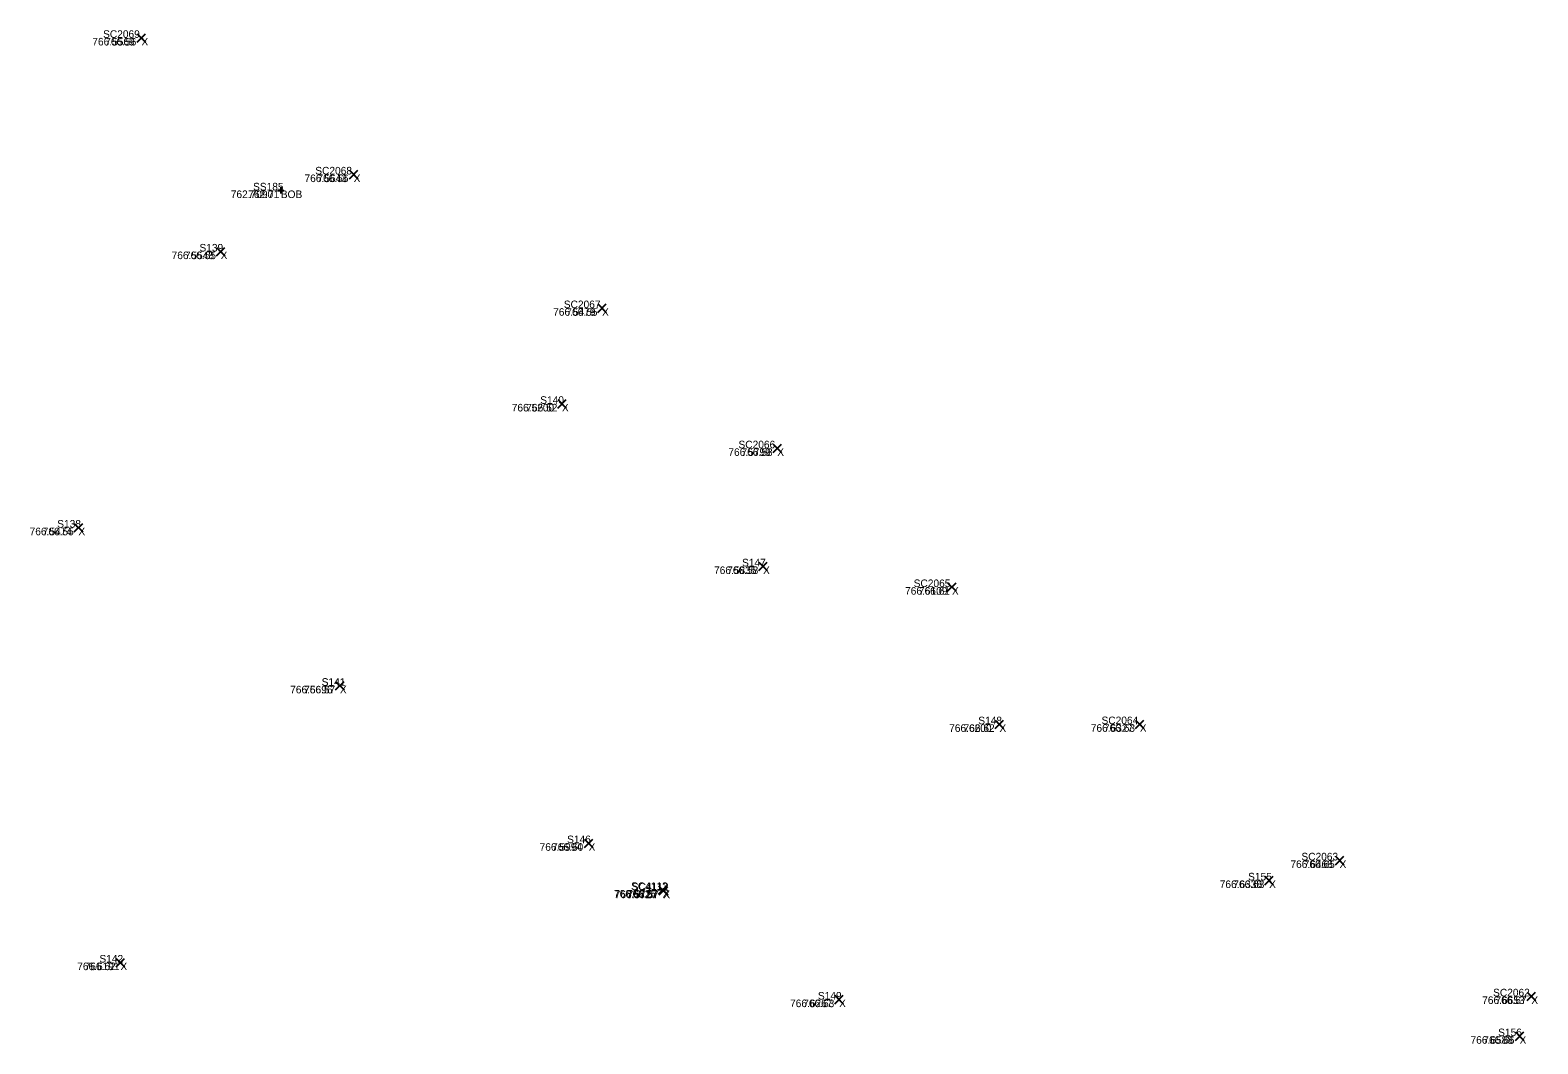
# Model space of a CAD drawing. Extents: x 1845019 to 1877956, y 680444 to 701081.
# Drawn here: x 1857583.62 to 1857595.52, y 694342.22 to 694350.22 of the extents above; entities that cross this region are included whole.
import ezdxf

# ---------------------------------------------------------------- set-up
doc = ezdxf.new("R2010")
doc.units = 0
for name, color, linetype in [('BR_X_SV_Bottom_of_Beam_Text', 7, 'Continuous'), ('SV_X_Random_Point', 7, 'Continuous'), ('SV_X_Text_Comment', 7, 'Continuous'), ('SV_X_Text_Elevation', 7, 'Continuous'), ('SV_X_Text_Name', 7, 'Continuous')]:
    doc.layers.add(name, color=color, linetype=linetype)

msp = doc.modelspace()

# ---------------------------------------------------------------- linework, layer by layer
at = {"layer": 'BR_X_SV_Bottom_of_Beam_Text'}
for p, q in [((1857585.572, 694348.951), (1857585.622, 694348.951)), ((1857585.572, 694348.951), (1857585.622, 694348.951)), ((1857585.597, 694348.976), (1857585.597, 694348.926)), ((1857585.597, 694348.976), (1857585.597, 694348.926)), ((1857585.597, 694348.951), (1857585.597, 694348.951)), ((1857585.597, 694348.951), (1857585.597, 694348.951))]:
    msp.add_line(p, q, dxfattribs=at)
at = {"layer": 'SV_X_Random_Point'}
for p, q in [((1857584.463, 694350.122), (1857584.53, 694350.188)), ((1857584.463, 694350.188), (1857584.53, 694350.122)), ((1857584.463, 694350.122), (1857584.53, 694350.188)), ((1857584.463, 694350.188), (1857584.53, 694350.122)), ((1857586.138, 694349.043), (1857586.205, 694349.11)), ((1857586.138, 694349.11), (1857586.205, 694349.043)), ((1857586.138, 694349.043), (1857586.205, 694349.11)), ((1857586.138, 694349.11), (1857586.205, 694349.043)), ((1857585.089, 694348.436), (1857585.156, 694348.502)), ((1857585.089, 694348.502), (1857585.156, 694348.436)), ((1857585.089, 694348.436), (1857585.156, 694348.502)), ((1857585.089, 694348.502), (1857585.156, 694348.436)), ((1857588.099, 694347.989), (1857588.166, 694348.055)), ((1857588.099, 694348.055), (1857588.166, 694347.989)), ((1857588.099, 694347.989), (1857588.166, 694348.055)), ((1857588.099, 694348.055), (1857588.166, 694347.989)), ((1857587.783, 694347.233), (1857587.85, 694347.3)), ((1857587.783, 694347.3), (1857587.85, 694347.233)), ((1857587.783, 694347.233), (1857587.85, 694347.3)), ((1857587.783, 694347.3), (1857587.85, 694347.233)), ((1857589.483, 694346.883), (1857589.549, 694346.949)), ((1857589.483, 694346.949), (1857589.549, 694346.883)), ((1857589.483, 694346.883), (1857589.549, 694346.949)), ((1857589.483, 694346.949), (1857589.549, 694346.883)), ((1857583.966, 694346.256), (1857584.033, 694346.323)), ((1857583.966, 694346.323), (1857584.033, 694346.256)), ((1857583.966, 694346.256), (1857584.033, 694346.323)), ((1857583.966, 694346.323), (1857584.033, 694346.256)), ((1857589.37, 694345.951), (1857589.437, 694346.018)), ((1857589.37, 694346.018), (1857589.437, 694345.951)), ((1857589.37, 694345.951), (1857589.437, 694346.018)), ((1857589.37, 694346.018), (1857589.437, 694345.951)), ((1857590.861, 694345.788), (1857590.928, 694345.854)), ((1857590.861, 694345.854), (1857590.928, 694345.788)), ((1857590.861, 694345.788), (1857590.928, 694345.854)), ((1857590.861, 694345.854), (1857590.928, 694345.788)), ((1857586.029, 694345.009), (1857586.096, 694345.076)), ((1857586.029, 694345.076), (1857586.096, 694345.009)), ((1857586.029, 694345.009), (1857586.096, 694345.076)), ((1857586.029, 694345.076), (1857586.096, 694345.009)), ((1857591.236, 694344.704), (1857591.303, 694344.771)), ((1857591.236, 694344.771), (1857591.303, 694344.704)), ((1857591.236, 694344.704), (1857591.303, 694344.771)), ((1857591.236, 694344.771), (1857591.303, 694344.704)), ((1857592.344, 694344.706), (1857592.411, 694344.772)), ((1857592.344, 694344.772), (1857592.411, 694344.706)), ((1857592.344, 694344.706), (1857592.411, 694344.772)), ((1857592.344, 694344.772), (1857592.411, 694344.706)), ((1857587.994, 694343.766), (1857588.061, 694343.833)), ((1857587.994, 694343.833), (1857588.061, 694343.766)), ((1857587.994, 694343.766), (1857588.061, 694343.833)), ((1857587.994, 694343.833), (1857588.061, 694343.766)), ((1857593.922, 694343.63), (1857593.989, 694343.697)), ((1857593.922, 694343.697), (1857593.989, 694343.63)), ((1857593.922, 694343.63), (1857593.989, 694343.697)), ((1857593.922, 694343.697), (1857593.989, 694343.63)), ((1857588.578, 694343.398), (1857588.645, 694343.464)), ((1857588.578, 694343.464), (1857588.645, 694343.398)), ((1857588.578, 694343.398), (1857588.645, 694343.464)), ((1857588.578, 694343.464), (1857588.645, 694343.398)), ((1857588.584, 694343.393), (1857588.651, 694343.459)), ((1857588.584, 694343.459), (1857588.651, 694343.393)), ((1857588.584, 694343.393), (1857588.651, 694343.459)), ((1857588.584, 694343.459), (1857588.651, 694343.393)), ((1857593.365, 694343.472), (1857593.432, 694343.539)), ((1857593.365, 694343.539), (1857593.432, 694343.472)), ((1857593.365, 694343.472), (1857593.432, 694343.539)), ((1857593.365, 694343.539), (1857593.432, 694343.472)), ((1857584.298, 694342.825), (1857584.364, 694342.891)), ((1857584.298, 694342.891), (1857584.364, 694342.825)), ((1857584.298, 694342.825), (1857584.364, 694342.891)), ((1857584.298, 694342.891), (1857584.364, 694342.825)), ((1857595.435, 694342.558), (1857595.502, 694342.624)), ((1857595.435, 694342.624), (1857595.502, 694342.558)), ((1857595.435, 694342.558), (1857595.502, 694342.624)), ((1857595.435, 694342.624), (1857595.502, 694342.558)), ((1857589.97, 694342.533), (1857590.037, 694342.6)), ((1857589.97, 694342.6), (1857590.037, 694342.533)), ((1857589.97, 694342.533), (1857590.037, 694342.6)), ((1857589.97, 694342.6), (1857590.037, 694342.533)), ((1857595.343, 694342.244), (1857595.41, 694342.311)), ((1857595.343, 694342.311), (1857595.41, 694342.244)), ((1857595.343, 694342.244), (1857595.41, 694342.311)), ((1857595.343, 694342.311), (1857595.41, 694342.244))]:
    msp.add_line(p, q, dxfattribs=at)

# ---------------------------------------------------------------- texts
at = {"layer": 'BR_X_SV_Bottom_of_Beam_Text'}
for s, p in [('762.7090', (1857585.202, 694348.891)), ('762.71', (1857585.34, 694348.891)), ('SS185', (1857585.378, 694348.951)), ('SS185', (1857585.378, 694348.951)), ('BOB', (1857585.597, 694348.891))]:
    msp.add_text(s, height=0.06, dxfattribs=at).set_placement(p)
at = {"layer": 'SV_X_Text_Comment'}
for p in [(1857584.497, 694350.095), (1857586.172, 694349.017), (1857585.122, 694348.409), (1857588.133, 694347.962), (1857587.816, 694347.207), (1857589.516, 694346.856), (1857583.999, 694346.23), (1857589.404, 694345.924), (1857590.895, 694345.761), (1857586.063, 694344.982), (1857591.27, 694344.678), (1857592.378, 694344.679), (1857588.027, 694343.74), (1857593.955, 694343.604), (1857593.399, 694343.446), (1857588.611, 694343.371), (1857588.617, 694343.366), (1857584.331, 694342.798), (1857590.004, 694342.506), (1857595.469, 694342.531), (1857595.376, 694342.217)]:
    msp.add_text('X', height=0.06, dxfattribs=at).set_placement(p)
at = {"layer": 'SV_X_Text_Elevation'}
for s, p in [('766.5569', (1857584.109, 694350.095)), ('766.56', (1857584.211, 694350.095)), ('766.5643', (1857585.784, 694349.017)), ('766.56', (1857585.886, 694349.017)), ('766.5548', (1857584.735, 694348.409)), ('766.55', (1857584.84, 694348.409)), ('766.5479', (1857587.747, 694347.962)), ('766.55', (1857587.851, 694347.962)), ('766.5200', (1857587.42, 694347.207)), ('766.52', (1857587.535, 694347.207)), ('766.5799', (1857589.13, 694346.856)), ('766.58', (1857589.234, 694346.856)), ('766.5474', (1857583.614, 694346.23)), ('766.55', (1857583.717, 694346.23)), ('766.5835', (1857589.017, 694345.924)), ('766.58', (1857589.121, 694345.924)), ('766.6109', (1857590.525, 694345.761)), ('766.61', (1857590.634, 694345.761)), ('766.5696', (1857585.671, 694344.982)), ('766.57', (1857585.781, 694344.982)), ('766.6200', (1857590.873, 694344.678)), ('766.62', (1857590.987, 694344.678)), ('766.6327', (1857591.991, 694344.679)), ('766.63', (1857592.095, 694344.679)), ('766.5994', (1857587.64, 694343.74)), ('766.60', (1857587.739, 694343.74)), ('766.6468', (1857593.567, 694343.604)), ('766.65', (1857593.672, 694343.604)), ('766.6338', (1857593.009, 694343.446)), ('766.63', (1857593.116, 694343.446)), ('766.5725', (1857588.227, 694343.371)), ('766.5727', (1857588.233, 694343.366)), ('766.57', (1857588.329, 694343.371)), ('766.57', (1857588.335, 694343.366)), ('766.6191', (1857583.99, 694342.798)), ('766.62', (1857584.048, 694342.798)), ('766.6267', (1857589.617, 694342.506)), ('766.63', (1857589.721, 694342.506)), ('766.6653', (1857595.081, 694342.531)), ('766.67', (1857595.186, 694342.531)), ('766.6588', (1857594.989, 694342.217)), ('766.66', (1857595.09, 694342.217))]:
    msp.add_text(s, height=0.06, dxfattribs=at).set_placement(p)
at = {"layer": 'SV_X_Text_Name'}
for s, p in [('SC2069', (1857584.194, 694350.155)), ('SC2069', (1857584.194, 694350.155)), ('SC2068', (1857585.869, 694349.077)), ('SC2068', (1857585.869, 694349.077)), ('S139', (1857584.955, 694348.469)), ('S139', (1857584.955, 694348.469)), ('SC2067', (1857587.831, 694348.022)), ('SC2067', (1857587.831, 694348.022)), ('S140', (1857587.645, 694347.267)), ('S140', (1857587.645, 694347.267)), ('SC2066', (1857589.21, 694346.916)), ('SC2066', (1857589.21, 694346.916)), ('S138', (1857583.832, 694346.29)), ('S138', (1857583.832, 694346.29)), ('S147', (1857589.238, 694345.984)), ('S147', (1857589.238, 694345.984)), ('SC2065', (1857590.593, 694345.821)), ('SC2065', (1857590.593, 694345.821)), ('S141', (1857585.919, 694345.042)), ('S141', (1857585.92, 694345.042)), ('S148', (1857591.103, 694344.738)), ('S148', (1857591.103, 694344.738)), ('SC2064', (1857592.076, 694344.739)), ('SC2064', (1857592.076, 694344.739)), ('S146', (1857587.857, 694343.8)), ('S146', (1857587.857, 694343.8)), ('SC2063', (1857593.654, 694343.664)), ('SC2063', (1857593.654, 694343.664)), ('SC4113', (1857588.362, 694343.431)), ('SC4113', (1857588.362, 694343.431)), ('SC4112', (1857588.368, 694343.426)), ('SC4112', (1857588.368, 694343.426)), ('S155', (1857593.233, 694343.506)), ('S155', (1857593.233, 694343.506)), ('S142', (1857584.165, 694342.858)), ('S142', (1857584.165, 694342.858)), ('S149', (1857589.837, 694342.566)), ('S149', (1857589.837, 694342.566)), ('SC2062', (1857595.167, 694342.591)), ('SC2062', (1857595.167, 694342.591)), ('S156', (1857595.207, 694342.277)), ('S156', (1857595.207, 694342.277))]:
    msp.add_text(s, height=0.06, dxfattribs=at).set_placement(p)

doc.saveas('drawing.dxf')
